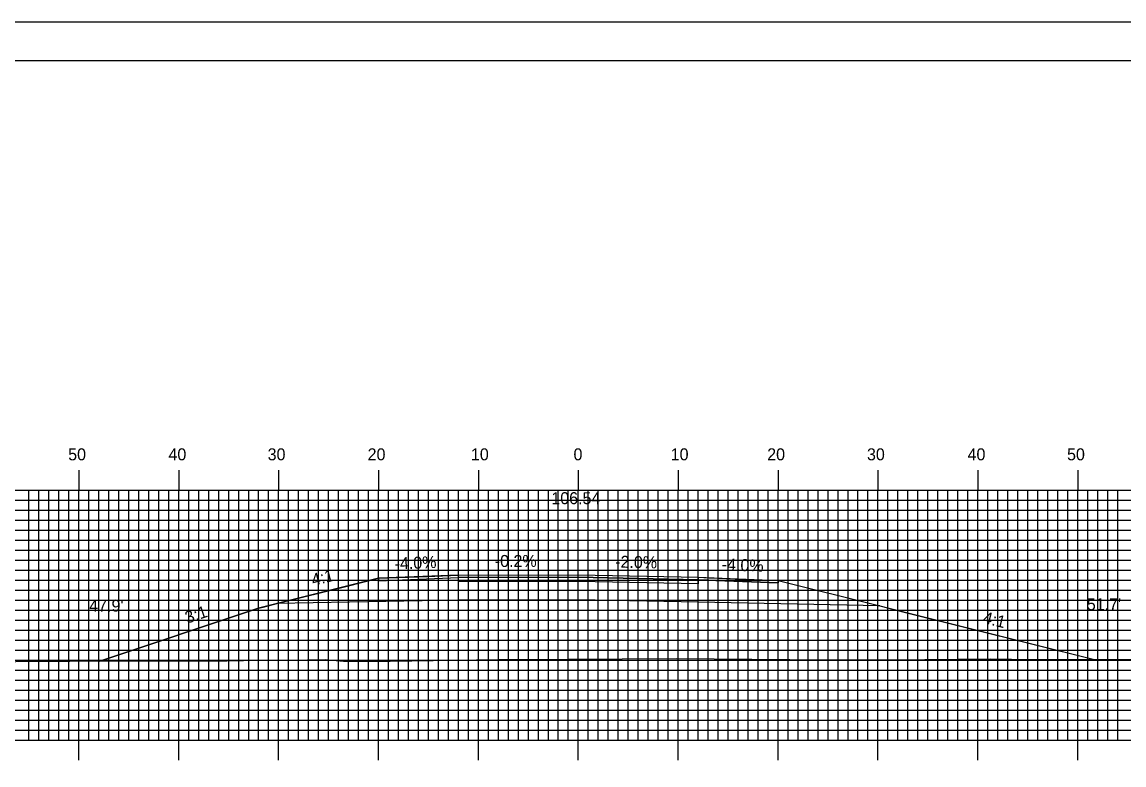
# Model space of a CAD drawing. Extents: x 1764939 to 1765282, y 442591 to 442811.
# Drawn here: x 1765049.2 to 1765159.5, y 442736.2 to 442810.5 of the extents above; entities that cross this region are included whole.
import ezdxf

# ---------------------------------------------------------------- set-up
doc = ezdxf.new("R2010")
doc.units = 0
for name, color, linetype in [('ANNOTATION', 7, 'Continuous'), ('BORDER', 7, 'Continuous'), ('D_Roadway_Centerline', 7, 'Continuous'), ('D_Roadway_Centerline_Text', 7, 'Continuous'), ('D_Roadway_Edge_Shoulder', 7, 'Continuous'), ('D_Roadway_Edge_TW', 7, 'Continuous'), ('D_Roadway_Pavement', 7, 'Continuous'), ('D_Roadway_SlopeLines', 7, 'Continuous'), ('D_Roadway_SubGrade', 7, 'Continuous'), ('D_Text_Standard', 7, 'Continuous'), ('H_V ANNOTATION', 7, 'Continuous'), ('MAJOR', 7, 'Continuous'), ('MINOR', 7, 'Continuous'), ('PLOT BOUNDARY', 7, 'Continuous'), ('S_Roadway_Centerline', 7, 'Continuous')]:
    doc.layers.add(name, color=color, linetype=linetype)

msp = doc.modelspace()

# ---------------------------------------------------------------- linework, layer by layer
at = {"layer": 'BORDER'}
msp.add_lwpolyline([(1764955.26, 442596.67), (1765275.26, 442596.67), (1765275.26, 442806.67), (1764955.26, 442806.67)], close=True, dxfattribs=at)
at = {"layer": 'D_Roadway_Centerline'}
msp.add_lwpolyline([(1765056.95, 442746.56), (1765056.95, 442746.56), (1765072.86, 442751.86), (1765073.31, 442751.98), (1765074.68, 442752.32), (1765081.72, 442754.08), (1765084.86, 442754.86), (1765088.89, 442755.02), (1765092.86, 442755.18), (1765104.86, 442755.21), (1765116.86, 442754.97), (1765117.96, 442754.92), (1765124.86, 442754.65), (1765135.03, 442752.1), (1765137.63, 442751.45), (1765156.55, 442746.72), (1765156.55, 442746.72)], dxfattribs=at)
at = {"layer": 'D_Roadway_Edge_Shoulder'}
for points in [[(1765092.86, 442755.18), (1765084.86, 442754.86), (1765084.86, 442754.61), (1765092.86, 442754.93)], [(1765116.86, 442754.97), (1765124.86, 442754.65), (1765124.86, 442754.4), (1765116.86, 442754.72)]]:
    msp.add_lwpolyline(points, close=True, dxfattribs=at)
at = {"layer": 'D_Roadway_Edge_TW'}
msp.add_lwpolyline([(1765092.86, 442754.93), (1765092.86, 442755.18), (1765104.86, 442755.21), (1765116.86, 442754.97), (1765116.86, 442754.72), (1765104.86, 442754.96)], close=True, dxfattribs=at)
at = {"layer": 'D_Roadway_Pavement'}
msp.add_lwpolyline([(1765092.86, 442754.52), (1765092.86, 442754.93), (1765104.86, 442754.96), (1765116.86, 442754.72), (1765116.86, 442754.3), (1765104.86, 442754.54)], close=True, dxfattribs=at)
at = {"layer": 'D_Roadway_SlopeLines'}
for points in [[(1765084.86, 442754.86), (1765072.86, 442751.86), (1765056.95, 442746.56)], [(1765124.86, 442754.65), (1765135.03, 442752.1), (1765156.55, 442746.72)]]:
    msp.add_lwpolyline(points, dxfattribs=at)
at = {"layer": 'D_Roadway_SubGrade'}
msp.add_lwpolyline([(1765092.86, 442752.68), (1765074.68, 442752.32), (1765084.86, 442754.86), (1765084.86, 442754.61), (1765092.86, 442754.93), (1765104.86, 442754.96), (1765116.86, 442754.72), (1765124.86, 442754.4), (1765124.86, 442754.65), (1765135.03, 442752.1), (1765116.86, 442752.47), (1765104.86, 442752.71)], close=True, dxfattribs=at)
at = {"layer": 'MAJOR'}
for p, q in [((1765054.86, 442765.67), (1765054.86, 442763.67)), ((1765064.86, 442765.67), (1765064.86, 442763.67)), ((1765074.86, 442765.67), (1765074.86, 442763.67)), ((1765084.86, 442765.67), (1765084.86, 442763.67)), ((1765094.86, 442765.67), (1765094.86, 442763.67)), ((1765104.86, 442765.67), (1765104.86, 442763.67)), ((1765114.86, 442765.67), (1765114.86, 442763.67)), ((1765124.86, 442765.67), (1765124.86, 442763.67)), ((1765134.86, 442765.67), (1765134.86, 442763.67)), ((1765144.86, 442765.67), (1765144.86, 442763.67)), ((1765154.86, 442765.67), (1765154.86, 442763.67)), ((1764964.86, 442763.67), (1765244.86, 442763.67)), ((1764964.86, 442763.67), (1765244.86, 442763.67)), ((1765054.86, 442738.67), (1765054.86, 442763.67)), ((1765064.86, 442738.67), (1765064.86, 442763.67)), ((1765074.86, 442738.67), (1765074.86, 442763.67)), ((1765084.86, 442738.67), (1765084.86, 442763.67)), ((1765094.86, 442738.67), (1765094.86, 442763.67)), ((1765104.86, 442738.67), (1765104.86, 442763.67)), ((1765114.86, 442738.67), (1765114.86, 442763.67)), ((1765124.86, 442738.67), (1765124.86, 442763.67)), ((1765134.86, 442738.67), (1765134.86, 442763.67)), ((1765144.86, 442738.67), (1765144.86, 442763.67)), ((1765154.86, 442738.67), (1765154.86, 442763.67)), ((1764964.86, 442758.67), (1765244.86, 442758.67)), ((1764964.86, 442753.67), (1765244.86, 442753.67)), ((1764964.86, 442748.67), (1765244.86, 442748.67)), ((1764964.86, 442743.67), (1765244.86, 442743.67)), ((1764964.86, 442738.67), (1765244.86, 442738.67)), ((1764964.86, 442738.67), (1765244.86, 442738.67)), ((1765054.86, 442736.66), (1765054.86, 442738.67)), ((1765064.86, 442736.66), (1765064.86, 442738.67)), ((1765074.86, 442736.66), (1765074.86, 442738.67)), ((1765084.86, 442736.66), (1765084.86, 442738.67)), ((1765094.86, 442736.66), (1765094.86, 442738.67)), ((1765104.86, 442736.66), (1765104.86, 442738.67)), ((1765114.86, 442736.66), (1765114.86, 442738.67)), ((1765124.86, 442736.66), (1765124.86, 442738.67)), ((1765134.86, 442736.66), (1765134.86, 442738.67)), ((1765144.86, 442736.66), (1765144.86, 442738.67)), ((1765154.86, 442736.66), (1765154.86, 442738.67))]:
    msp.add_line(p, q, dxfattribs=at)
at = {"layer": 'MINOR'}
for p, q in [((1765049.86, 442738.67), (1765049.86, 442763.67)), ((1765050.86, 442738.67), (1765050.86, 442763.67)), ((1765051.86, 442738.67), (1765051.86, 442763.67)), ((1765052.86, 442738.67), (1765052.86, 442763.67)), ((1765053.86, 442738.67), (1765053.86, 442763.67)), ((1765055.86, 442738.67), (1765055.86, 442763.67)), ((1765056.86, 442738.67), (1765056.86, 442763.67)), ((1765057.86, 442738.67), (1765057.86, 442763.67)), ((1765058.86, 442738.67), (1765058.86, 442763.67)), ((1765059.86, 442738.67), (1765059.86, 442763.67)), ((1765060.86, 442738.67), (1765060.86, 442763.67)), ((1765061.86, 442738.67), (1765061.86, 442763.67)), ((1765062.86, 442738.67), (1765062.86, 442763.67)), ((1765063.86, 442738.67), (1765063.86, 442763.67)), ((1765065.86, 442738.67), (1765065.86, 442763.67)), ((1765066.86, 442738.67), (1765066.86, 442763.67)), ((1765067.86, 442738.67), (1765067.86, 442763.67)), ((1765068.86, 442738.67), (1765068.86, 442763.67)), ((1765069.86, 442738.67), (1765069.86, 442763.67)), ((1765070.86, 442738.67), (1765070.86, 442763.67)), ((1765071.86, 442738.67), (1765071.86, 442763.67)), ((1765072.86, 442738.67), (1765072.86, 442763.67)), ((1765073.86, 442738.67), (1765073.86, 442763.67)), ((1765075.86, 442738.67), (1765075.86, 442763.67)), ((1765076.86, 442738.67), (1765076.86, 442763.67)), ((1765077.86, 442738.67), (1765077.86, 442763.67)), ((1765078.86, 442738.67), (1765078.86, 442763.67)), ((1765079.86, 442738.67), (1765079.86, 442763.67)), ((1765080.86, 442738.67), (1765080.86, 442763.67)), ((1765081.86, 442738.67), (1765081.86, 442763.67)), ((1765082.86, 442738.67), (1765082.86, 442763.67)), ((1765083.86, 442738.67), (1765083.86, 442763.67)), ((1765085.86, 442738.67), (1765085.86, 442763.67)), ((1765086.86, 442738.67), (1765086.86, 442763.67)), ((1765087.86, 442738.67), (1765087.86, 442763.67)), ((1765088.86, 442738.67), (1765088.86, 442763.67)), ((1765089.86, 442738.67), (1765089.86, 442763.67)), ((1765090.86, 442738.67), (1765090.86, 442763.67)), ((1765091.86, 442738.67), (1765091.86, 442763.67)), ((1765092.86, 442738.67), (1765092.86, 442763.67)), ((1765093.86, 442738.67), (1765093.86, 442763.67)), ((1765095.86, 442738.67), (1765095.86, 442763.67)), ((1765096.86, 442738.67), (1765096.86, 442763.67)), ((1765097.86, 442738.67), (1765097.86, 442763.67)), ((1765098.86, 442738.67), (1765098.86, 442763.67)), ((1765099.86, 442738.67), (1765099.86, 442763.67)), ((1765100.86, 442738.67), (1765100.86, 442763.67)), ((1765101.86, 442738.67), (1765101.86, 442763.67)), ((1765102.86, 442738.67), (1765102.86, 442763.67)), ((1765103.86, 442738.67), (1765103.86, 442763.67)), ((1765105.86, 442738.67), (1765105.86, 442763.67)), ((1765106.86, 442738.67), (1765106.86, 442763.67)), ((1765107.86, 442738.67), (1765107.86, 442763.67)), ((1765108.86, 442738.67), (1765108.86, 442763.67)), ((1765109.86, 442738.67), (1765109.86, 442763.67)), ((1765110.86, 442738.67), (1765110.86, 442763.67)), ((1765111.86, 442738.67), (1765111.86, 442763.67)), ((1765112.86, 442738.67), (1765112.86, 442763.67)), ((1765113.86, 442738.67), (1765113.86, 442763.67)), ((1765115.86, 442738.67), (1765115.86, 442763.67)), ((1765116.86, 442738.67), (1765116.86, 442763.67)), ((1765117.86, 442738.67), (1765117.86, 442763.67)), ((1765118.86, 442738.67), (1765118.86, 442763.67)), ((1765119.86, 442738.67), (1765119.86, 442763.67)), ((1765120.86, 442738.67), (1765120.86, 442763.67)), ((1765121.86, 442738.67), (1765121.86, 442763.67)), ((1765122.86, 442738.67), (1765122.86, 442763.67)), ((1765123.86, 442738.67), (1765123.86, 442763.67)), ((1765125.86, 442738.67), (1765125.86, 442763.67)), ((1765126.86, 442738.67), (1765126.86, 442763.67)), ((1765127.86, 442738.67), (1765127.86, 442763.67)), ((1765128.86, 442738.67), (1765128.86, 442763.67)), ((1765129.86, 442738.67), (1765129.86, 442763.67)), ((1765130.86, 442738.67), (1765130.86, 442763.67)), ((1765131.86, 442738.67), (1765131.86, 442763.67)), ((1765132.86, 442738.67), (1765132.86, 442763.67)), ((1765133.86, 442738.67), (1765133.86, 442763.67)), ((1765135.86, 442738.67), (1765135.86, 442763.67)), ((1765136.86, 442738.67), (1765136.86, 442763.67)), ((1765137.86, 442738.67), (1765137.86, 442763.67)), ((1765138.86, 442738.67), (1765138.86, 442763.67)), ((1765139.86, 442738.67), (1765139.86, 442763.67)), ((1765140.86, 442738.67), (1765140.86, 442763.67)), ((1765141.86, 442738.67), (1765141.86, 442763.67)), ((1765142.86, 442738.67), (1765142.86, 442763.67)), ((1765143.86, 442738.67), (1765143.86, 442763.67)), ((1765145.86, 442738.67), (1765145.86, 442763.67)), ((1765146.86, 442738.67), (1765146.86, 442763.67)), ((1765147.86, 442738.67), (1765147.86, 442763.67)), ((1765148.86, 442738.67), (1765148.86, 442763.67)), ((1765149.86, 442738.67), (1765149.86, 442763.67)), ((1765150.86, 442738.67), (1765150.86, 442763.67)), ((1765151.86, 442738.67), (1765151.86, 442763.67)), ((1765152.86, 442738.67), (1765152.86, 442763.67)), ((1765153.86, 442738.67), (1765153.86, 442763.67)), ((1765155.86, 442738.67), (1765155.86, 442763.67)), ((1765156.86, 442738.67), (1765156.86, 442763.67)), ((1765157.86, 442738.67), (1765157.86, 442763.67)), ((1765158.86, 442738.67), (1765158.86, 442763.67)), ((1764964.86, 442762.67), (1765244.86, 442762.67)), ((1764964.86, 442761.67), (1765244.86, 442761.67)), ((1764964.86, 442760.67), (1765244.86, 442760.67)), ((1764964.86, 442759.67), (1765244.86, 442759.67)), ((1764964.86, 442757.67), (1765244.86, 442757.67)), ((1764964.86, 442756.67), (1765244.86, 442756.67)), ((1764964.86, 442755.67), (1765244.86, 442755.67)), ((1764964.86, 442754.67), (1765244.86, 442754.67)), ((1764964.86, 442752.67), (1765244.86, 442752.67)), ((1764964.86, 442751.67), (1765244.86, 442751.67)), ((1764964.86, 442750.67), (1765244.86, 442750.67)), ((1764964.86, 442749.67), (1765244.86, 442749.67)), ((1764964.86, 442747.67), (1765244.86, 442747.67)), ((1764964.86, 442746.67), (1765244.86, 442746.67)), ((1764964.86, 442745.67), (1765244.86, 442745.67)), ((1764964.86, 442744.67), (1765244.86, 442744.67)), ((1764964.86, 442742.67), (1765244.86, 442742.67)), ((1764964.86, 442741.67), (1765244.86, 442741.67)), ((1764964.86, 442740.67), (1765244.86, 442740.67)), ((1764964.86, 442739.67), (1765244.86, 442739.67))]:
    msp.add_line(p, q, dxfattribs=at)
at = {"layer": 'PLOT BOUNDARY'}
msp.add_lwpolyline([(1764939.07, 442590.55), (1765279.07, 442590.55), (1765279.07, 442810.55), (1764939.07, 442810.55)], close=True, dxfattribs=at)
at = {"layer": 'S_Roadway_Centerline'}
msp.add_lwpolyline([(1765043.15, 442746.5), (1765053.94, 442746.55), (1765060.98, 442746.58), (1765069.68, 442746.61), (1765071.35, 442746.63), (1765073.43, 442746.66), (1765074.5, 442746.66), (1765077.76, 442746.69), (1765079.51, 442746.72), (1765081.35, 442746.57), (1765083.85, 442746.54), (1765094.66, 442746.69), (1765096.83, 442746.73), (1765098.47, 442746.72), (1765114.67, 442746.82), (1765129.83, 442746.7), (1765132.59, 442746.7), (1765136.27, 442746.7), (1765146.08, 442746.79), (1765150.36, 442746.73), (1765161.32, 442746.72)], dxfattribs=at)

# ---------------------------------------------------------------- texts
at = {"layer": 'ANNOTATION'}
for s, rotation, p in [('-4.0%', 2.2909, (1765086.49, 442755.73)), ('-0.2%', 0.1098, (1765096.5, 442755.99)), ('-2.0%', 358.8543, (1765108.54, 442755.93)), ('-4.0%', 357.7095, (1765119.2, 442755.67)), ('4:1', 14.0377, (1765078.31, 442754.09)), ('3:1', 18.4372, (1765065.72, 442750.32)), ('4:1', 345.9638, (1765145.3, 442750.4))]:
    msp.add_text(s, height=1.2, rotation=rotation, dxfattribs=at).set_placement(p)
at = {"layer": 'D_Roadway_Centerline'}
for s, p in [('C', (1765104.85, 442755.21)), ('L', (1765104.86, 442755.2))]:
    msp.add_text(s, height=0.0146, dxfattribs=at).set_placement(p)
at = {"layer": 'D_Roadway_Centerline_Text'}
msp.add_text('106.54', height=1.2, dxfattribs=at).set_placement((1765102.16, 442762.28))
at = {"layer": 'D_Text_Standard'}
for s, p in [("47.9'", (1765055.9, 442751.52)), ("51.7'", (1765155.77, 442751.66))]:
    msp.add_text(s, height=1.2, dxfattribs=at).set_placement(p)
at = {"layer": 'H_V ANNOTATION'}
for s, p in [('50', (1765053.79, 442766.67)), ('40', (1765063.83, 442766.67)), ('30', (1765073.76, 442766.67)), ('20', (1765083.77, 442766.67)), ('10', (1765094.11, 442766.67)), ('0', (1765104.38, 442766.67)), ('10', (1765114.11, 442766.67)), ('20', (1765123.77, 442766.67)), ('30', (1765133.76, 442766.67)), ('40', (1765143.83, 442766.67)), ('50', (1765153.79, 442766.67))]:
    msp.add_text(s, height=1.2, dxfattribs=at).set_placement(p)

doc.saveas('drawing.dxf')
